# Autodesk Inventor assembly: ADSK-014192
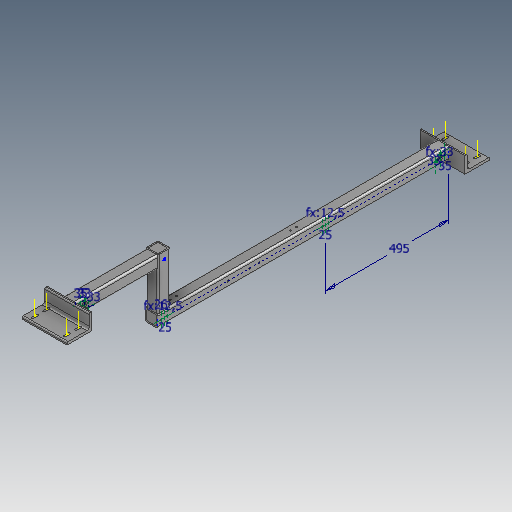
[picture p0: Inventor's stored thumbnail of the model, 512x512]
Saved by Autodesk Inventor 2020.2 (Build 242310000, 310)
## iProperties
_FrameDoc: Frame Assembly
_Version: 15.0.0
Part Number: ADSK-014192
Description: Phantom-Baugruppe
Document SubType Name: Baugruppe
Designer: lutzd
Mass: 15989.1 g
Surface Area: 7123.65 cm^2
Volume: 2036.83 cm^3
Density: 7.85 g/cm^3
DocNumber: ADSK-014173
Folder: .
Dimensions: 270x1698x180 mm
Mass: 15,989 kg
Title: Gestellbaugruppen
Author: lutzd
Revision Number: -
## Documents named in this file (8)
- D:\07 - DEMODATEN\OTX 2019 - Dataset - UPDATE - Dez2019\Designs\07-Packing machine\500277\Frame\ADSK-014192.iam
- D:\07 - DEMODATEN\OTX 2019 - Dataset - UPDATE - Dez2019\Designs\07-Packing machine\500277\Frame\ADSK-014193.ipt
- D:\07 - DEMODATEN\OTX 2019 - Dataset - UPDATE - Dez2019\Designs\07-Packing machine\500277\Frame\ADSK-014195.ipt
- D:\07 - DEMODATEN\OTX 2019 - Dataset - UPDATE - Dez2019\Designs\07-Packing machine\500277\Frame\ADSK-014196.ipt
- D:\07 - DEMODATEN\OTX 2019 - Dataset - UPDATE - Dez2019\Designs\07-Packing machine\500277\Frame\ADSK-014194.ipt
- D:\07 - DEMODATEN\OTX 2019 - Dataset - UPDATE - Dez2019\Designs\07-Packing machine\500277\Frame\ADSK-014179.ipt
- D:\07 - DEMODATEN\OTX 2019 - Dataset - UPDATE - Dez2019\Designs\07-Packing machine\500277\Frame\Plate Gerundete Ecken (mm) 1570183079462.ipt
- D:\07 - DEMODATEN\OTX 2019 - Dataset - UPDATE - Dez2019\Designs\07-Packing machine\500277\Frame\Plate Gerundete Ecken (mm) 1570183210581.ipt
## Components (8 placed, 4 different names)
1. Gestellreferenzmodell
2. DIN 50 x 50 x 5:1
3. DIN 50 x 50 x 5:4
4. DIN 50 x 50 x 5:5
5. Gerundete Ecken (mm) 5 x 39,384472 x 39,384472:1
6. Gerundete Ecken (mm) 5 x 39,384472 x 39,384472:2
7. DIN L100x65x10:1
8. DIN L100x65x10:3
